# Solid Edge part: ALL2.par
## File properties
Author: f_grande
Template: Normal.par
Last saved by: f_grande
Revision: 3
Application: Solid Edge
Material: Alluminio, 1060
Stile della faccia: Alluminio
Stile di riempimento: ANSI38(Alluminio)
Stile virtuale: Alluminio lucidato
Coef. of Thermal Exp: 0.0
Thermal Conductivity: 221.0
Specific Heat: 920.0
Modulus of Elasticity: 68947570000.0
Poisson's Ratio: 0.33
Yield Stress: 27579028.0
Ultimate Stress: 68947570.0
Elongation: 0.0
Tipo di contenuto documento: 0
Densità: 2712,000 kg/m^3
Precisione: 0,990
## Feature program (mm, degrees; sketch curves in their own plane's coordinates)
sketch for "unnamed Protrusion 1" #1 plane through (0, 0, 0) normal (0, 0, 1) x-axis (1, 0, 0)
  line (1.5, 8.5) -> (1.5, 6.8374)
  arc centre (0, 0) radius 7 from (1.5, 6.8374) to (6.8374, 1.5) cw
  line (6.8374, 1.5) -> (8.5, 1.5)
  line (8.5, 1.5) -> (8.5, 8)
  line (8.5, 8) -> (18.5, 8)
  line (18.5, 8) -> (18.5, 18.5)
  line (18.5, 18.5) -> (8.0281, 18.5)
  line (8.0281, 18.5) -> (8.0281, 8.5)
  line (8.0281, 8.5) -> (1.5, 8.5)
sketch for "unnamed Protrusion 1" #2 plane through (0, 0, 0) normal (0, 0, 1) x-axis (1, 0, 0)
  line (20, 19) -> (20, 5)
  line (20, 5) -> (18.5, 5)
  line (18.5, 5) -> (18.5, 6.5)
  line (18.5, 6.5) -> (10, 6.5)
  line (10, 6.5) -> (10, 0)
  line (10, 0) -> (6, 0)
  arc centre (-0.937, -0.937) radius 7 from (0, 6) to (6, 0) cw
  line (0, 6) -> (0, 10)
  line (6.5281, 10) -> (0, 10)
  line (6.5281, 18.5) -> (6.5281, 10)
  line (5.0281, 18.5) -> (6.5281, 18.5)
  line (5.0281, 20) -> (5.0281, 18.5)
  line (5.0281, 20) -> (19, 20)
  arc centre (19, 19) radius 1 from (19, 20) to (20, 19) cw
  dimension (linear) = 10
extrude "unnamed Protrusion 1" add finite 700 along +normal
body pattern "unnamed BodyPattern 1"
pattern "unnamed Pattern 1"
body pattern "unnamed BodyPattern 2"
pattern "unnamed Pattern 2"
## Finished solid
Body 1: solid body, 82 faces, 240 edges, 160 vertices.
  Faces by surface: plane 70, cylinder 12
  Edges by curve: line 216, circle 24
Bounding box of the edges (mm): 40.000 x 40.000 x 700.000, from (-20, -20, 0) to (20, 20, 700).
Cylindrical faces by radius (mm): R1 x4, R7 x8
Planar faces by outward normal: +x 17, +y 17, +z 1, -x 17, -y 17, -z 1
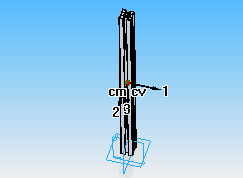
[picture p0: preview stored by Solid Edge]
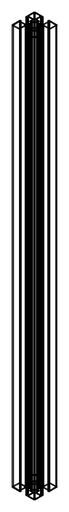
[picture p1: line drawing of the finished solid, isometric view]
